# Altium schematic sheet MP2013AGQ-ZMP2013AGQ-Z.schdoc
size 127 x 101 mm
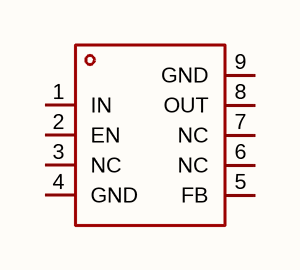
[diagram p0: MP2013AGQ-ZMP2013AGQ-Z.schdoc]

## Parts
U?  mp2013agq-z  [QFN-8_L3.0-W3.0-P0.65-TL-EP2.5]  (value not drawn)

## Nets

Not connected (* = marked no-connect by the designer): U? 1(IN) 2(EN) 3(NC) 4(GND) 5(FB) 6(NC) 7(NC) 8(OUT) 9(GND)

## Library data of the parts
U? = mp2013agq-z: 输出类型:可调;工作电压:40V;输出电压:1.215V~15V;输出电流:150mA;电源纹波抑制比(PSRR):-;输出极性:正极;; Manufacturer: MPS(芯源); AddInBom: yes; ModelId: 7d7b0c6373f54773b7915f82dc80757a; ModelTransform: 118.18874,118.11,0,0,0,0,0,0,0; Output Type: 可调; Voltage - Supply: 40V; Output Current: 150mA; Voltage Dropout: 850mV@(150mA); standby current: 9uA; Output Configuration: 正极; Number of Outputs: 1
